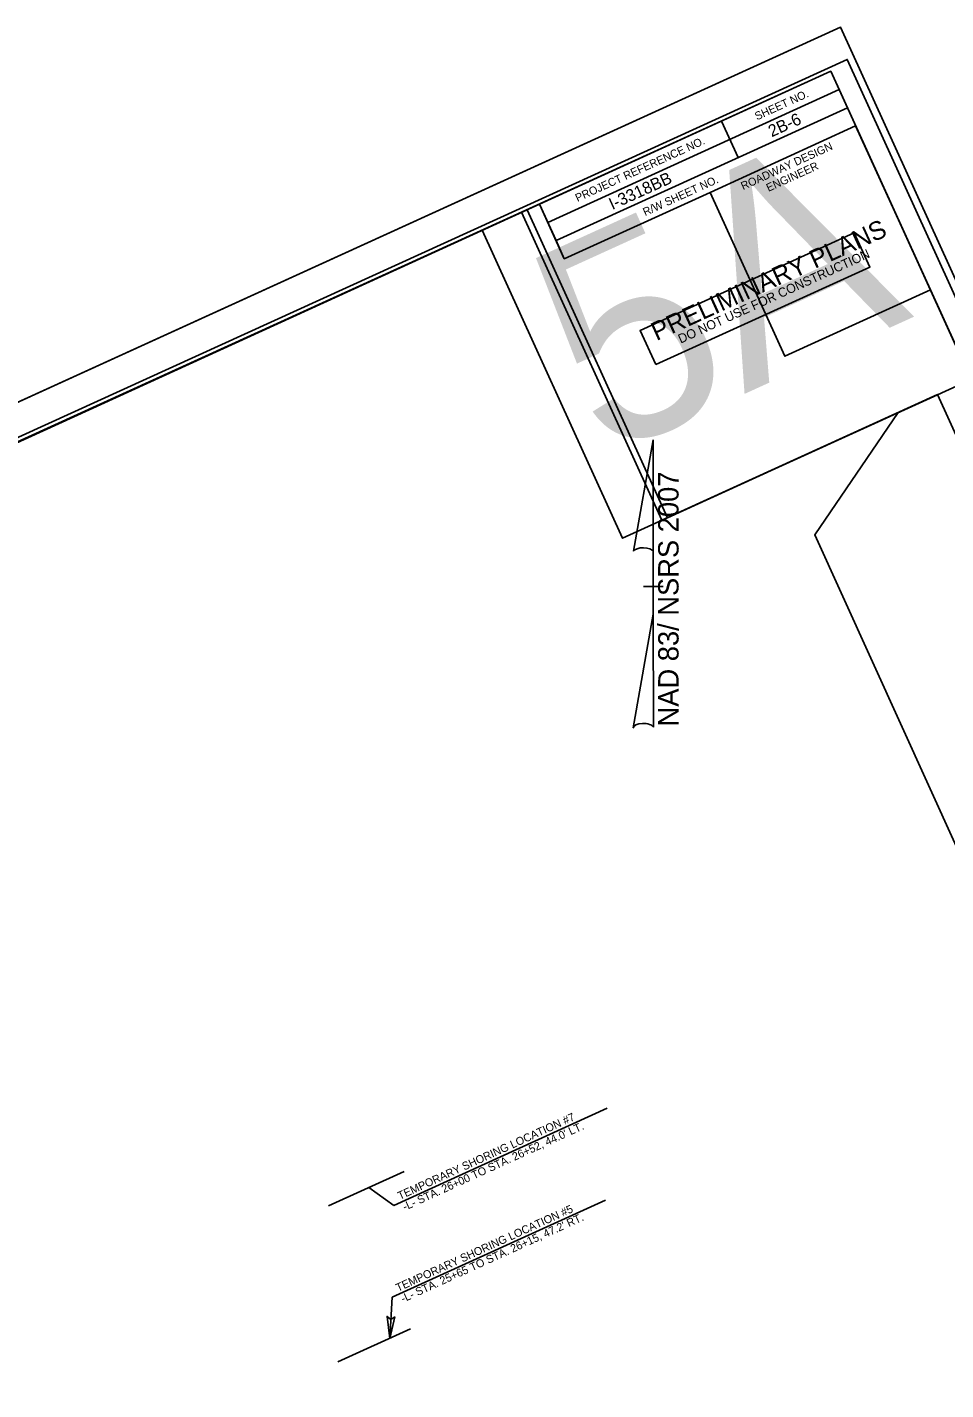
# Model space of a CAD drawing. Extents: x 2247910 to 2249896, y 662531 to 664266.
# Drawn here: x 2248933 to 2249507, y 663375 to 664226 of the extents above; entities that cross this region are included whole.
import ezdxf

# ---------------------------------------------------------------- set-up
doc = ezdxf.new("R2010")
doc.units = 0
for name, color, linetype in [('Prop North Arrow NAD83 for Plan Sheets CELL', 7, 'Continuous'), ('Prop Temporary Shoring', 7, 'Continuous'), ('Prop Temporary Shoring Leader Line', 7, 'Continuous'), ('Prop Terminator CELL', 7, 'Continuous'), ('Sheet Clip Boundary CELL', 7, 'Continuous'), ('Sheet Cutting Line CELL', 7, 'Continuous'), ('Sheet Data Field CELL', 7, 'Continuous'), ('Sheet Layout Plan Border', 7, 'Continuous'), ('Sheet Plan CELL', 7, 'Continuous'), ('Sheet Plan Layout CELL', 7, 'Continuous'), ('Sheet Plot Border Inside CELL', 7, 'Continuous'), ('Sheet Plot Border Outside CELL', 7, 'Continuous'), ('Sheet Sticker Preliminary CELL', 7, 'Continuous')]:
    doc.layers.add(name, color=color, linetype=linetype)

msp = doc.modelspace()

# ---------------------------------------------------------------- linework, layer by layer
at = {"layer": 'Prop North Arrow NAD83 for Plan Sheets CELL'}
for p, q in [((2249312.07, 663898.49), (2249324.37, 663968.01)), ((2249324.45, 663968.01), (2249324.37, 663968.01)), ((2249324.45, 663968.01), (2249324.37, 663968.01)), ((2249324.45, 663968.01), (2249324.45, 663896.31)), ((2249324.45, 663859.11), (2249324.45, 663898.41)), ((2249324.45, 663896.31), (2249324.45, 663898.34)), ((2249318.45, 663876.51), (2249318.37, 663876.51)), ((2249323.77, 663876.51), (2249318.45, 663876.51)), ((2249318.52, 663876.51), (2249330.52, 663876.51)), ((2249324.45, 663859.11), (2249311.92, 663788.24)), ((2249324.52, 663788.54), (2249324.45, 663859.11))]:
    msp.add_line(p, q, dxfattribs=at)
for centre, start_param, end_param in [((2249318.28, 663897.74), 0.216388, 2.908219), ((2249318.28, 663787.99), 0.201328, 3.141593)]:
    msp.add_ellipse(centre, major_axis=(6.35, -0.05), ratio=0.461098, start_param=start_param, end_param=end_param, dxfattribs=at)
at = {"layer": 'Prop Temporary Shoring'}
for p, q in [((2249121.44, 663489.53), (2249168.78, 663511.03)), ((2249127.29, 663392.02), (2249172.82, 663412.69))]:
    msp.add_line(p, q, dxfattribs=at)
at = {"layer": 'Prop Temporary Shoring Leader Line'}
for p, q in [((2249162.35, 663489.87), (2249295.54, 663550.56)), ((2249162.35, 663489.87), (2249146.7, 663501)), ((2249161.21, 663432.45), (2249294.48, 663493.18)), ((2249161.21, 663432.45), (2249159.82, 663406.79))]:
    msp.add_line(p, q, dxfattribs=at)
at = {"layer": 'Prop Terminator CELL'}
msp.add_lwpolyline([(2249162.87, 663420.14), (2249159.82, 663406.79), (2249158.16, 663420.48), (2249160.46, 663418.62)], close=True, dxfattribs=at)
at = {"layer": 'Sheet Clip Boundary CELL'}
msp.add_lwpolyline([(2248241.67, 663371.06), (2248489.82, 662824.78), (2248551.22, 662641.58), (2248585.88, 662667.26), (2249638.09, 663136.85), (2249825.2, 663222.11), (2249759.42, 663344.83), (2249697.59, 663317.15), (2249673.42, 663362.44), (2249425.27, 663908.72), (2249477.5, 663985.14), (2249333.25, 663919.41), (2249245.56, 664111.86), (2248806.18, 663911.31), (2248826.45, 663856.95), (2248820.45, 663848.41), (2248540.82, 663728.18), (2248517.28, 663777.91), (2248115.83, 663597.06)], close=True, dxfattribs=at)
at = {"layer": 'Sheet Cutting Line CELL'}
msp.add_line((2249441.45, 664225.83), (2247909.5, 663527.75), dxfattribs=at)
at = {"layer": 'Sheet Layout Plan Border'}
msp.add_lwpolyline([(2248198.13, 663481.51), (2248575.77, 662652.77), (2249849.75, 663233.3), (2249502.05, 663996.33), (2249329.83, 663917.85), (2249242.13, 664110.3), (2248140.38, 663608.25)], close=True, dxfattribs=at)
at = {"layer": 'Sheet Plan CELL'}
for p, q in [((2249258.45, 664103.96), (2249440.49, 664186.9)), ((2249263.66, 664092.55), (2249445.68, 664175.52)), ((2249263.66, 664092.55), (2249445.68, 664175.52)), ((2249367.05, 664167.15), (2249377.46, 664144.42)), ((2249268.84, 664081.19), (2249359.88, 664122.68)), ((2249359.88, 664122.68), (2249406.53, 664020.34)), ((2249263.66, 664092.55), (2249268.84, 664081.19))]:
    msp.add_line(p, q, dxfattribs=at)
for points in [[(2249435.32, 664198.33), (2248070.33, 663576.33), (2248505.72, 662620.85), (2249870.7, 663242.85)], [(2249253.26, 664115.38), (2249435.32, 664198.33), (2249445.68, 664175.52), (2249263.66, 664092.55)], [(2249359.88, 664122.68), (2249450.86, 664164.15), (2249497.53, 664061.77), (2249406.53, 664020.29)], [(2248505.72, 662620.85), (2248070.31, 663576.29), (2249253.26, 664115.38), (2249268.84, 664081.19), (2249359.88, 664122.68), (2249406.53, 664020.29), (2249497.53, 664061.77), (2249870.7, 663242.85)]]:
    msp.add_lwpolyline(points, close=True, dxfattribs=at)
at = {"layer": 'Sheet Plan Layout CELL'}
for points in [[(2249305.27, 663906.66), (2249523.01, 664005.88), (2249435.34, 664198.34), (2249217.58, 664099.11)], [(2248070.31, 663576.29), (2248505.72, 662620.85), (2249870.68, 663242.84), (2249522.99, 664005.87), (2249305.27, 663906.66), (2249217.58, 664099.11)]]:
    msp.add_lwpolyline(points, close=True, dxfattribs=at)
at = {"layer": 'Sheet Plot Border Inside CELL'}
msp.add_lwpolyline([(2248367.09, 662554.92), (2249883.1, 663245.75), (2249445.65, 664205.77), (2247929.62, 663514.94)], close=True, dxfattribs=at)
at = {"layer": 'Sheet Plot Border Outside CELL'}
msp.add_lwpolyline([(2248363.56, 662531.33), (2249895.5, 663229.41), (2249441.45, 664225.83), (2247909.5, 663527.75)], close=True, dxfattribs=at)
at = {"layer": 'Sheet Sticker Preliminary CELL'}
msp.add_lwpolyline([(2249325.96, 664015.07), (2249316.22, 664036.45), (2249449.99, 664097.41), (2249459.73, 664076.02)], close=True, dxfattribs=at)

# ---------------------------------------------------------------- texts
at = {"layer": 'Prop North Arrow NAD83 for Plan Sheets CELL'}
msp.add_text('NAD 83/ NSRS 2007', height=12.75, rotation=90, dxfattribs=at).set_placement((2249340.23, 663789.06))
at = {"layer": 'Prop Temporary Shoring'}
for s, p in [('TEMPORARY SHORING LOCATION #7', (2249166.11, 663493.24)), ("-L- STA. 26+00 TO STA. 26+52, 44.0' LT.", (2249169.22, 663486.42)), ('TEMPORARY SHORING LOCATION #5', (2249164.97, 663435.82)), ("-L- STA. 25+65 TO STA. 26+15, 47.2' RT.", (2249168.08, 663429))]:
    msp.add_text(s, height=5, rotation=24.49794, dxfattribs=at).set_placement(p)
at = {"layer": 'Sheet Data Field CELL'}
for s, p in [('2B-6', (2249398.36, 664157.04)), ('I-3318BB', (2249298.8, 664111.6))]:
    msp.add_text(s, height=7.5, rotation=24.49795, dxfattribs=at).set_placement(p)
at = {"layer": 'Sheet Plan CELL'}
for s, height, p in [('SHEET NO.', 5, (2249389.2, 664167.62)), ('PROJECT REFERENCE NO.', 5.0001, (2249277.08, 664116.65)), ('ROADWAY DESIGN', 5.0001, (2249380.54, 664124.04)), ('ENGINEER', 5, (2249396.39, 664122.98)), ('R/W SHEET NO.', 5.0001, (2249319.34, 664107.83))]:
    msp.add_text(s, height=height, rotation=24.49795, dxfattribs=at).set_placement(p)
at = {"layer": 'Sheet Plan Layout CELL'}
msp.add_text('5A', height=131.25, rotation=24.49794, dxfattribs=at).set_placement((2249292.31, 663956.16))
at = {"layer": 'Sheet Sticker Preliminary CELL'}
for s, height, p in [('PRELIMINARY PLANS', 11.52, (2249326.43, 664029.73)), ('DO NOT USE FOR CONSTRUCTION', 5.76, (2249341.54, 664028.15))]:
    msp.add_text(s, height=height, rotation=24.49794, dxfattribs=at).set_placement(p)

doc.saveas('drawing.dxf')
